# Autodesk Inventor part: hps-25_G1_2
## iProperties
Shininess: 20.0
Length Units: 11269
Angle Units: 11279
Time Units: 11290
Mass Units: 11283
Length Display Precision: 2
Angle Display Precision: 2
Company: Microsonic
Part Number: hps-25_G1_2
Material: ABS Plastik
Document SubType Name: Modellieren
Description: mic+ 25 Sensor
Checked By: Alves
Created: 2007-03
Designer: Tanck
Manufacturer: Standard
Standards Organization: Custom
Density: 0.0
Volumn: 0.0
Area: 0.0
PropertySet Name: Model Information
Control State: 0
Master: False
Checked Out: False
BESTELLNUMMER: mic+600/XX/TC
ME: ST
Title: hps_25_G1_2
Author: Tanck
Comments: keine Bemerkung
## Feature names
1. Grundkörper [Revolution]
2. Bohrung1 [Hole]
3. Pole [Extrusion]
4. Abrundung Pole [Fillet]
5. Verdrehsicherung [Extrusion]
6. Extrusion4
7. Drehung5 [Revolution]
8. Drehung6 [Revolution]
9. Rundung2 [Fillet]
10. Fase2 [Chamfer]
11. O-Ring Vertiefung [Extrusion]
12. Rundung3 [Fillet]
13. Umdrehung7 [Revolution]
